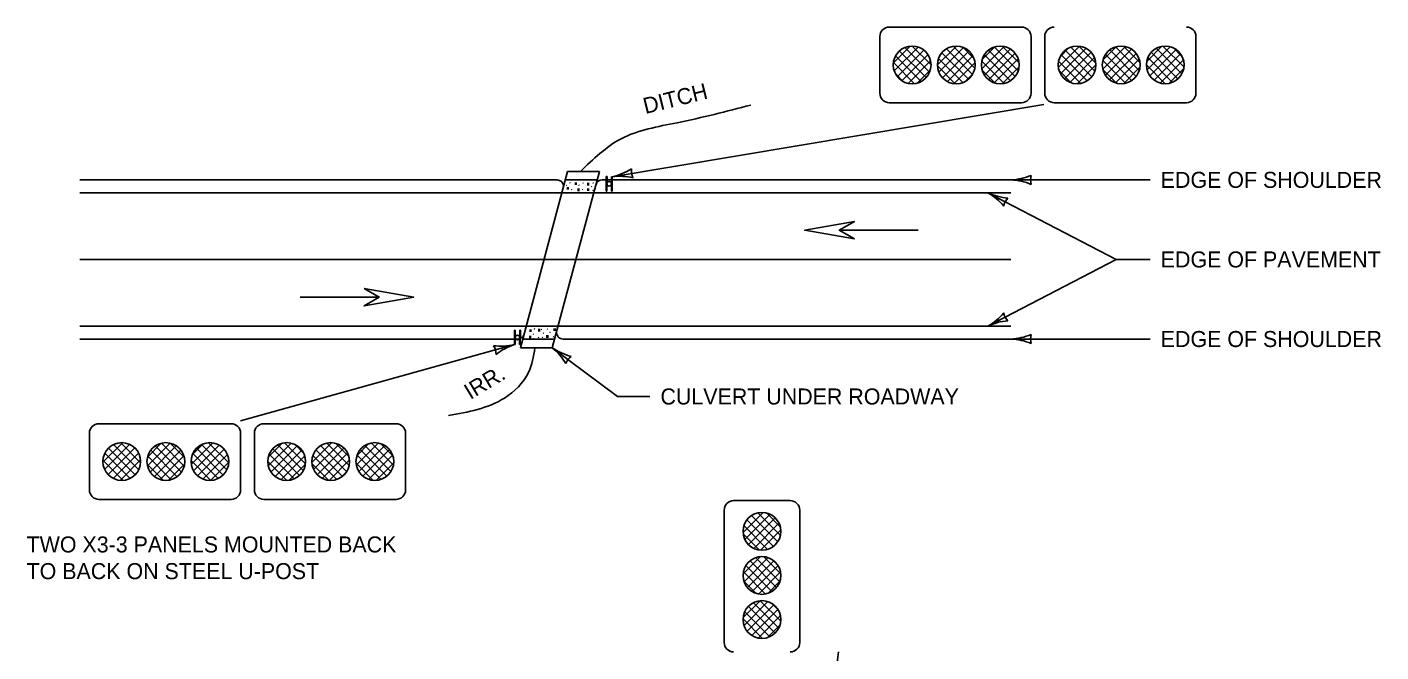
# Model space of a CAD drawing. Extents: x 49991.4 to 50021, y 49987.6 to 50011.4.
# Drawn here: x 50005.18 to 50010.25, y 49991.45 to 49993.79 of the extents above; entities that cross this region are included whole.
import ezdxf

# ---------------------------------------------------------------- set-up
doc = ezdxf.new("R2010")
doc.units = 0
for name, color, linetype in [('Level 1', 7, 'Continuous'), ('Level 2', 7, 'Continuous'), ('Level 3', 7, 'Continuous'), ('Level 4', 7, 'Continuous'), ('Level 5', 7, 'Continuous')]:
    doc.layers.add(name, color=color, linetype=linetype)

msp = doc.modelspace()

# ---------------------------------------------------------------- linework, layer by layer
at = {"layer": 'Level 1'}
for p, q in [((50008.3739, 49993.5463), (50008.3739, 49993.7588)), ((50008.4093, 49993.7942), (50008.9052, 49993.7942)), ((50008.9406, 49993.7588), (50008.9406, 49993.5463)), ((50008.9923, 49993.5463), (50008.9923, 49993.7588)), ((50009.559, 49993.7588), (50009.559, 49993.5463)), ((50008.4246, 49993.6601), (50008.4872, 49993.7228)), ((50008.4279, 49993.6304), (50008.5172, 49993.7196)), ((50008.4395, 49993.6088), (50008.5387, 49993.708)), ((50008.5471, 49993.6049), (50008.4473, 49993.7046)), ((50008.56, 49993.6251), (50008.4675, 49993.7176)), ((50008.5658, 49993.6524), (50008.4948, 49993.7234)), ((50008.5896, 49993.6523), (50008.6607, 49993.7234)), ((50008.5952, 49993.6248), (50008.688, 49993.7176)), ((50008.7058, 49993.5986), (50008.6063, 49993.6981)), ((50008.6082, 49993.6047), (50008.7082, 49993.7047)), ((50008.721, 49993.6165), (50008.6242, 49993.7133)), ((50008.73, 49993.6405), (50008.6482, 49993.7223)), ((50008.7266, 49993.677), (50008.6849, 49993.7187)), ((50008.7563, 49993.638), (50008.8399, 49993.7217)), ((50008.7576, 49993.6725), (50008.8055, 49993.7203)), ((50008.7659, 49993.6145), (50008.8635, 49993.7122)), ((50008.8809, 49993.6086), (50008.7815, 49993.7079)), ((50008.7816, 49993.5972), (50008.881, 49993.6965)), ((50008.8926, 49993.6299), (50008.8029, 49993.7197)), ((50008.8958, 49993.6599), (50008.8326, 49993.723)), ((50009.0431, 49993.6438), (50009.1221, 49993.7228)), ((50009.0496, 49993.6834), (50009.0827, 49993.7164)), ((50009.0511, 49993.6187), (50009.1472, 49993.7148)), ((50009.0657, 49993.6002), (50009.1656, 49993.7001)), ((50009.1686, 49993.6082), (50009.069, 49993.7078)), ((50009.1804, 49993.6295), (50009.0904, 49993.7195)), ((50009.1839, 49993.6592), (50009.1199, 49993.7231)), ((50009.2096, 49993.6369), (50009.2943, 49993.7216)), ((50009.2101, 49993.6705), (50009.2607, 49993.7211)), ((50009.2195, 49993.6137), (50009.3176, 49993.7118)), ((50009.2354, 49993.5965), (50009.3347, 49993.6958)), ((50009.3349, 49993.6096), (50009.2357, 49993.7089)), ((50009.3463, 49993.6314), (50009.2575, 49993.7202)), ((50009.3489, 49993.6618), (50009.2879, 49993.7228)), ((50009.3743, 49993.6656), (50009.4309, 49993.7222)), ((50009.3756, 49993.6338), (50009.4627, 49993.7209)), ((50009.3862, 49993.6114), (50009.4851, 49993.7102)), ((50009.4915, 49993.6001), (50009.3915, 49993.7001)), ((50009.5061, 49993.6186), (50009.41, 49993.7147)), ((50009.5142, 49993.6436), (50009.435, 49993.7228)), ((50009.5079, 49993.683), (50009.4744, 49993.7165)), ((50008.5035, 49993.5823), (50008.4247, 49993.661)), ((50008.5285, 49993.5904), (50008.4328, 49993.6861)), ((50008.4568, 49993.5931), (50008.5544, 49993.6907)), ((50008.4801, 49993.5833), (50008.5641, 49993.6673)), ((50008.6563, 49993.5819), (50008.5895, 49993.6486)), ((50008.6849, 49993.5864), (50008.5941, 49993.6772)), ((50008.6269, 49993.5903), (50008.7227, 49993.6861)), ((50008.6521, 49993.5824), (50008.7304, 49993.6607)), ((50008.8399, 49993.5834), (50008.7564, 49993.6669)), ((50008.8635, 49993.5929), (50008.7659, 49993.6905)), ((50008.8031, 49993.5856), (50008.8927, 49993.6751)), ((50008.8328, 49993.5821), (50008.8958, 49993.6451)), ((50009.1275, 49993.5831), (50009.044, 49993.6667)), ((50009.1511, 49993.5926), (50009.0535, 49993.6903)), ((50009.0859, 49993.5873), (50009.1787, 49993.6801)), ((50009.1134, 49993.5817), (50009.1842, 49993.6525)), ((50009.2947, 49993.5836), (50009.2097, 49993.6686)), ((50009.3178, 49993.5936), (50009.2197, 49993.6917)), ((50009.2571, 49993.5851), (50009.3461, 49993.6741)), ((50009.2874, 49993.5823), (50009.349, 49993.6439)), ((50009.4437, 49993.5817), (50009.3731, 49993.6523)), ((50009.4714, 49993.5872), (50009.3786, 49993.6799)), ((50009.4029, 49993.5949), (50009.5016, 49993.6936)), ((50009.4252, 49993.5842), (50009.5123, 49993.6712)), ((50008.4631, 49993.5895), (50008.432, 49993.6207)), ((50008.5144, 49993.5845), (50008.5629, 49993.6329)), ((50008.6924, 49993.5896), (50008.7234, 49993.6206)), ((50008.8053, 49993.5849), (50008.7579, 49993.6323)), ((50009.0927, 49993.5848), (50009.0456, 49993.632)), ((50009.2615, 49993.5838), (50009.2099, 49993.6354)), ((50009.457, 49993.5829), (50009.5135, 49993.6394)), ((50008.9052, 49993.5109), (50008.4093, 49993.5109)), ((50009.5235, 49993.5109), (50009.0277, 49993.5109)), ((50007.0264, 49992.5926), (50007.2034, 49993.2531)), ((50007.1458, 49992.5928), (50007.3226, 49993.2531)), ((50007.2034, 49993.2531), (50007.3226, 49993.2531)), ((50007.1951, 49993.222), (50007.1951, 49993.222)), ((50007.1951, 49993.222), (50007.3143, 49993.222)), ((50007.3483, 49993.234), (50007.3477, 49993.1802)), ((50007.351, 49993.234), (50007.3483, 49993.234)), ((50007.351, 49993.234), (50007.3504, 49993.1802)), ((50007.3679, 49993.2338), (50007.3672, 49993.1799)), ((50007.3706, 49993.2338), (50007.3679, 49993.2338)), ((50007.3706, 49993.2338), (50007.3699, 49993.1799)), ((50005.3747, 49993.1739), (50008.8653, 49993.1739)), ((50007.3477, 49993.1802), (50007.3504, 49993.1802)), ((50007.3672, 49993.1799), (50007.3699, 49993.1799)), ((50008.5179, 49993.0335), (50008.2218, 49993.0335)), ((50006.2011, 49992.7829), (50006.4972, 49992.7829)), ((50005.3747, 49992.6739), (50008.8653, 49992.6739)), ((50007.0043, 49992.659), (50007.0036, 49992.6051)), ((50007.007, 49992.6589), (50007.0043, 49992.659)), ((50007.007, 49992.6589), (50007.0063, 49992.605)), ((50007.0238, 49992.6587), (50007.0232, 49992.6048)), ((50007.0265, 49992.6586), (50007.0238, 49992.6587)), ((50007.0265, 49992.6586), (50007.0259, 49992.6047)), ((50007.0036, 49992.6051), (50007.0063, 49992.605)), ((50007.0232, 49992.6048), (50007.0259, 49992.6047)), ((50007.0264, 49992.5926), (50007.1458, 49992.5928)), ((50007.0353, 49992.6258), (50007.1546, 49992.6258)), ((50005.446, 49992.3085), (50005.9419, 49992.3085)), ((50006.0643, 49992.3085), (50006.5602, 49992.3085)), ((50005.4106, 49992.0606), (50005.4106, 49992.2731)), ((50005.4609, 49992.1643), (50005.5342, 49992.2376)), ((50005.4672, 49992.1374), (50005.561, 49992.2313)), ((50005.5956, 49992.1364), (50005.5013, 49992.2308)), ((50005.6024, 49992.1627), (50005.5276, 49992.2376)), ((50005.628, 49992.1506), (50005.7131, 49992.2358)), ((50005.6282, 49992.1839), (50005.6798, 49992.2356)), ((50005.638, 49992.1276), (50005.7362, 49992.2258)), ((50005.7555, 49992.1271), (50005.6572, 49992.2254)), ((50005.7658, 49992.15), (50005.6801, 49992.2357)), ((50005.7659, 49992.183), (50005.7129, 49992.2359)), ((50005.7922, 49992.1562), (50005.8729, 49992.2369)), ((50005.7967, 49992.1938), (50005.8352, 49992.2323)), ((50005.8007, 49992.1317), (50005.8974, 49992.2284)), ((50005.9258, 49992.1357), (50005.8311, 49992.2305)), ((50005.9329, 49992.1618), (50005.8571, 49992.2375)), ((50005.9201, 49992.2077), (50005.9027, 49992.225)), ((50005.9773, 49992.2731), (50005.9773, 49992.0606)), ((50006.0289, 49992.0606), (50006.0289, 49992.2731)), ((50006.0811, 49992.1835), (50006.1333, 49992.2357)), ((50006.0811, 49992.1503), (50006.1664, 49992.2357)), ((50006.0912, 49992.1274), (50006.1895, 49992.2257)), ((50006.2123, 49992.1333), (50006.1164, 49992.2292)), ((50006.2203, 49992.1583), (50006.1414, 49992.2372)), ((50006.2135, 49992.1982), (50006.1815, 49992.2303)), ((50006.2445, 49992.1636), (50006.3185, 49992.2376)), ((50006.251, 49992.1371), (50006.345, 49992.2311)), ((50006.3749, 49992.1286), (50006.277, 49992.2265)), ((50006.3845, 49992.1522), (50006.3006, 49992.2361)), ((50006.3834, 49992.1863), (50006.3347, 49992.235)), ((50006.411, 49992.1535), (50006.4939, 49992.2364)), ((50006.4132, 49992.1888), (50006.4586, 49992.2342)), ((50006.4203, 49992.1297), (50006.5177, 49992.2271)), ((50006.5407, 49992.1296), (50006.4432, 49992.2271)), ((50006.55, 49992.1533), (50006.467, 49992.2364)), ((50006.548, 49992.1885), (50006.5022, 49992.2343)), ((50006.5956, 49992.2731), (50006.5956, 49992.0606)), ((50005.5626, 49992.1032), (50005.468, 49992.1979)), ((50005.4813, 49992.1184), (50005.5807, 49992.2179)), ((50005.582, 49992.117), (50005.4818, 49992.2171)), ((50005.4996, 49992.1037), (50005.5949, 49992.1989)), ((50005.5253, 49992.0963), (50005.6022, 49992.1732)), ((50005.5844, 49992.2139), (50005.578, 49992.2202)), ((50005.7174, 49992.099), (50005.6291, 49992.1873)), ((50005.7394, 49992.1102), (50005.6403, 49992.2093)), ((50005.654, 49992.1105), (50005.7533, 49992.2098)), ((50005.6758, 49992.0992), (50005.7646, 49992.188)), ((50005.8926, 49992.1028), (50005.7982, 49992.1971)), ((50005.912, 49992.1164), (50005.8118, 49992.2166)), ((50005.8156, 49992.1135), (50005.9156, 49992.2135)), ((50005.8362, 49992.101), (50005.9281, 49992.1928)), ((50006.1777, 49992.1017), (50006.0848, 49992.1946)), ((50006.1978, 49992.1147), (50006.0977, 49992.2147)), ((50006.1073, 49992.1104), (50006.2065, 49992.2095)), ((50006.1292, 49992.0992), (50006.2177, 49992.1877)), ((50006.3376, 49992.0997), (50006.2481, 49992.1892)), ((50006.3591, 49992.1113), (50006.2597, 49992.2107)), ((50006.2645, 49992.1175), (50006.3646, 49992.2176)), ((50006.2836, 49992.1035), (50006.3786, 49992.1985)), ((50006.3095, 49992.0963), (50006.3859, 49992.1727)), ((50006.5041, 49992.1), (50006.4137, 49992.1904)), ((50006.5253, 49992.1119), (50006.4256, 49992.2116)), ((50006.4357, 49992.112), (50006.5354, 49992.2117)), ((50006.4569, 49992.1001), (50006.5473, 49992.1906)), ((50005.5366, 49992.0962), (50005.461, 49992.1718)), ((50005.4905, 49992.1092), (50005.4744, 49992.1252)), ((50005.5684, 49992.1063), (50005.5923, 49992.1302)), ((50005.6866, 49992.0968), (50005.6269, 49992.1565)), ((50005.7063, 49992.0966), (50005.7672, 49992.1575)), ((50005.8661, 49992.0961), (50005.7915, 49992.1708)), ((50005.8644, 49992.0961), (50005.933, 49992.1646)), ((50006.1502, 49992.096), (50006.0791, 49992.1672)), ((50006.1598, 49992.0967), (50006.2201, 49992.157)), ((50006.3078, 49992.0964), (50006.2448, 49992.1594)), ((50006.3536, 49992.1073), (50006.3748, 49992.1285)), ((50006.4747, 49992.0963), (50006.4099, 49992.1611)), ((50006.486, 49992.0962), (50006.5511, 49992.1612)), ((50005.9419, 49992.0252), (50005.446, 49992.0252)), ((50006.5602, 49992.0252), (50006.0643, 49992.0252)), ((50007.8257, 49992.0206), (50008.0382, 49992.0206)), ((50007.7903, 49991.4893), (50007.7903, 49991.9852)), ((50007.8612, 49991.9015), (50007.936, 49991.9762)), ((50007.868, 49991.8752), (50007.9623, 49991.9695)), ((50008.001, 49991.8895), (50007.916, 49991.9745)), ((50008.0006, 49991.9229), (50007.9494, 49991.9742)), ((50008.0736, 49991.9852), (50008.0736, 49991.4893)), ((50007.9532, 49991.838), (50007.8644, 49991.9268)), ((50007.975, 49991.8493), (50007.8757, 49991.9486)), ((50007.8789, 49991.9522), (50007.8841, 49991.9575)), ((50007.8816, 49991.8557), (50007.9818, 49991.9559)), ((50007.991, 49991.8663), (50007.8928, 49991.9646)), ((50007.9009, 49991.8418), (50007.9956, 49991.9366)), ((50007.9228, 49991.8353), (50007.8617, 49991.8964)), ((50007.927, 49991.8349), (50008.0026, 49991.9105)), ((50007.973, 49991.8478), (50007.9896, 49991.8644)), ((50007.8613, 49991.7459), (50007.9263, 49991.8109)), ((50007.8652, 49991.7167), (50007.9555, 49991.807)), ((50007.9691, 49991.6799), (50007.8717, 49991.7774)), ((50007.8771, 49991.6955), (50007.9767, 49991.7951)), ((50007.9867, 49991.6954), (50007.8871, 49991.795)), ((50007.8947, 49991.68), (50007.9922, 49991.7775)), ((50007.9987, 49991.7165), (50007.9082, 49991.807)), ((50008.0026, 49991.7457), (50007.9374, 49991.8109)), ((50007.9452, 49991.6707), (50007.8624, 49991.7535)), ((50007.91, 49991.6729), (50007.8646, 49991.7182)), ((50007.9185, 49991.6707), (50008.0015, 49991.7537)), ((50007.9538, 49991.6729), (50007.9994, 49991.7186)), ((50007.8615, 49991.5823), (50007.9246, 49991.6454)), ((50007.8648, 49991.5525), (50007.9544, 49991.6421)), ((50007.8764, 49991.531), (50007.9759, 49991.6305)), ((50007.981, 49991.5238), (50007.8809, 49991.624)), ((50007.9951, 49991.5428), (50007.8998, 49991.6381)), ((50008.0025, 49991.5685), (50007.9255, 49991.6455)), ((50007.9927, 49991.6114), (50007.9684, 49991.6357)), ((50007.9345, 49991.5042), (50007.8612, 49991.5774)), ((50007.9612, 49991.5105), (50007.8675, 49991.6043)), ((50007.8938, 49991.5153), (50007.9916, 49991.6131)), ((50007.9172, 49991.5057), (50008.0012, 49991.5897)), ((50007.9515, 49991.5069), (50008, 49991.5553))]:
    msp.add_line(p, q, dxfattribs=at)
for points in [[(50008.2787, 49993.0007), (50008.0925, 49993.0335), (50008.2787, 49993.0665), (50008.2219, 49993.0335)], [(50006.4403, 49992.8157), (50006.6265, 49992.7829), (50006.4403, 49992.7499), (50006.4971, 49992.7829)]]:
    msp.add_lwpolyline(points, close=True, dxfattribs=at)
for centre, radius in [((50008.495, 49993.6525), 0.0708), ((50008.6603, 49993.6525), 0.0708), ((50008.8255, 49993.6525), 0.0708), ((50009.1134, 49993.6526), 0.0708), ((50009.2787, 49993.6526), 0.0708), ((50009.4439, 49993.6526), 0.0708), ((50007.3591, 49993.207), 0.00844), ((50007.0151, 49992.6318), 0.00844), ((50005.5317, 49992.1669), 0.0708), ((50005.697, 49992.1669), 0.0708), ((50005.8622, 49992.1669), 0.0708), ((50006.15, 49992.1669), 0.0708), ((50006.3153, 49992.1669), 0.0708), ((50006.4805, 49992.1669), 0.0708), ((50007.9319, 49991.9055), 0.0708), ((50007.9319, 49991.7403), 0.0708), ((50007.9319, 49991.575), 0.0708)]:
    msp.add_circle(centre, radius, dxfattribs=at)
for centre, start, end in [((50008.4093, 49993.7588), 90, 180), ((50008.9052, 49993.7588), 0, 90), ((50009.0277, 49993.7588), 90, 180), ((50009.5236, 49993.7588), 0, 90), ((50008.4093, 49993.5463), 180, 270), ((50008.9052, 49993.5463), 270, 360), ((50009.0277, 49993.5463), 180, 270), ((50009.5235, 49993.5463), 270, 0), ((50005.446, 49992.2731), 90, 180), ((50005.9419, 49992.2731), 0, 90), ((50006.0643, 49992.2731), 90, 180), ((50006.5602, 49992.2731), 0, 90), ((50005.446, 49992.0606), 180, 270), ((50005.9419, 49992.0606), 270, 0), ((50006.0643, 49992.0606), 180, 270), ((50006.5602, 49992.0606), 270, 360), ((50007.8257, 49991.9852), 90, 180), ((50008.0382, 49991.9852), 0, 90), ((50007.8257, 49991.4893), 180, 270), ((50008.0382, 49991.4893), 270, 0)]:
    msp.add_arc(centre, 0.0354, start, end, dxfattribs=at)
for points in [[(50007.2513, 49993.2531), (50007.4042, 49993.376), (50007.614, 49993.436), (50007.8898, 49993.5019)], [(50006.7567, 49992.3388), (50006.9665, 49992.4048), (50007.0564, 49992.5007), (50007.0806, 49992.5927)]]:
    msp.add_spline(points, degree=3, dxfattribs=at)
at = {"layer": 'Level 3'}
for p, q in [((50007.3706, 49993.2338), (50008.9883, 49993.5044)), ((50009.387, 49993.222), (50008.8656, 49993.222)), ((50008.7788, 49993.1739), (50009.2594, 49992.9239)), ((50008.7788, 49992.6739), (50009.2594, 49992.9239)), ((50009.387, 49992.9239), (50009.2594, 49992.9239)), ((50007.0036, 49992.6051), (50005.9772, 49992.3192)), ((50007.3901, 49992.4106), (50007.1458, 49992.5928)), ((50009.387, 49992.6258), (50008.8653, 49992.6258)), ((50007.5114, 49992.4106), (50007.3901, 49992.4106))]:
    msp.add_line(p, q, dxfattribs=at)
for centre, radius, start, end in [((50007.3207, 49993.4614), 0.233, 282.3658, 301.6157), ((50007.497, 49993.2551), 0.0548, 171.6774, 207.3997), ((50008.8541, 49993.4547), 0.233, 272.8273, 292.0772), ((50008.9938, 49993.222), 0.0548, 162.1388, 197.8612), ((50007.3984, 49993.0132), 0.2223, 76.9945, 97.1781), ((50008.8564, 49992.9999), 0.2223, 67.456, 87.6395), ((50008.6682, 49992.9811), 0.2223, 39.9733, 60.1568), ((50008.876, 49993.3857), 0.233, 245.3446, 264.5945), ((50008.8925, 49993.1147), 0.0548, 134.6561, 170.3785), ((50008.6612, 49992.875), 0.233, 300.31, 319.5598), ((50008.8732, 49992.4726), 0.2223, 94.9387, 115.1222), ((50008.8925, 49992.7331), 0.0548, 189.6215, 225.3439), ((50008.8538, 49992.8585), 0.233, 272.8273, 292.0772), ((50008.9935, 49992.6258), 0.0548, 162.1388, 197.8612), ((50006.9527, 49992.8215), 0.2223, 263.0595, 283.243), ((50006.8801, 49992.5706), 0.0548, 357.7423, 33.4647), ((50007.0773, 49992.384), 0.233, 108.4308, 127.6807), ((50007.0056, 49992.4202), 0.2223, 30.7296, 50.9131), ((50007.2757, 49992.7862), 0.233, 236.1009, 255.3507), ((50008.8561, 49992.4037), 0.2223, 67.456, 87.6395), ((50007.2486, 49992.5161), 0.0548, 125.4124, 161.1348), ((50007.9964, 49991.4631), 0.2223, 337.456, 357.6395)]:
    msp.add_arc(centre, radius, start, end, dxfattribs=at)
at = {"layer": 'Level 4'}
for p, q in [((50005.3747, 49993.222), (50007.1637, 49993.222)), ((50007.3325, 49993.222), (50008.8653, 49993.222)), ((50005.3747, 49992.6259), (50007.0166, 49992.6259)), ((50007.1863, 49992.6258), (50008.8653, 49992.6258))]:
    msp.add_line(p, q, dxfattribs=at)
for centre, start, end in [((50007.1637, 49993.1976), 355.6314, 90), ((50007.333, 49993.1976), 91.1101, 162.3356), ((50007.0166, 49992.6503), 270, 344.9057), ((50007.1863, 49992.6502), 170.7302, 270)]:
    msp.add_arc(centre, 0.0244, start, end, dxfattribs=at)
at = {"layer": 'Level 5'}
msp.add_line((50005.3747, 49992.9239), (50008.8653, 49992.9239), dxfattribs=at)

# ---------------------------------------------------------------- texts
at = {"layer": 'Level 1'}
for p in [(50007.1936, 49993.2042), (50007.2066, 49993.2133), (50007.2127, 49993.1876), (50007.2405, 49993.2042), (50007.2537, 49993.188), (50007.2558, 49993.212), (50007.2873, 49993.1992), (50007.2935, 49993.2124), (50007.2927, 49993.1851), (50007.0687, 49992.6296), (50007.069, 49992.6458), (50007.0732, 49992.666), (50007.0883, 49992.6338), (50007.1, 49992.6639), (50007.1034, 49992.6347), (50007.107, 49992.65), (50007.1217, 49992.6654), (50007.1317, 49992.6533), (50007.144, 49992.6365)]:
    msp.add_text('.', height=0.03, rotation=315, dxfattribs=at).set_placement(p)
for p in [(50007.1913, 49993.1848), (50007.2212, 49993.2022), (50007.2315, 49993.1794), (50007.2671, 49993.1798), (50007.2675, 49993.2003), (50007.0494, 49992.6279), (50007.0508, 49992.6518), (50007.0832, 49992.654), (50007.1143, 49992.6297), (50007.1417, 49992.6554)]:
    msp.add_text('.', height=0.07, dxfattribs=at).set_placement(p)
at = {"layer": 'Level 2'}
for s, rotation, p in [('DITCH', 13.8636, (50007.4948, 49993.4684)), ('IRR.', 31.0843, (50006.8385, 49992.397))]:
    msp.add_text(s, height=0.06, rotation=rotation, dxfattribs=at).set_placement(p)
for s, p in [('EDGE OF SHOULDER', (50009.427, 49993.192)), ('EDGE OF PAVEMENT', (50009.427, 49992.8939)), ('EDGE OF SHOULDER', (50009.427, 49992.5958)), ('CULVERT UNDER ROADWAY', (50007.5514, 49992.3806)), ('TWO X3-3 PANELS MOUNTED BACK', (50005.1749, 49991.8264)), ('TO BACK ON STEEL U-POST', (50005.1749, 49991.7264))]:
    msp.add_text(s, height=0.06, dxfattribs=at).set_placement(p)

doc.saveas('drawing.dxf')
